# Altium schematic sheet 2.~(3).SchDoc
size 420 x 297 mm
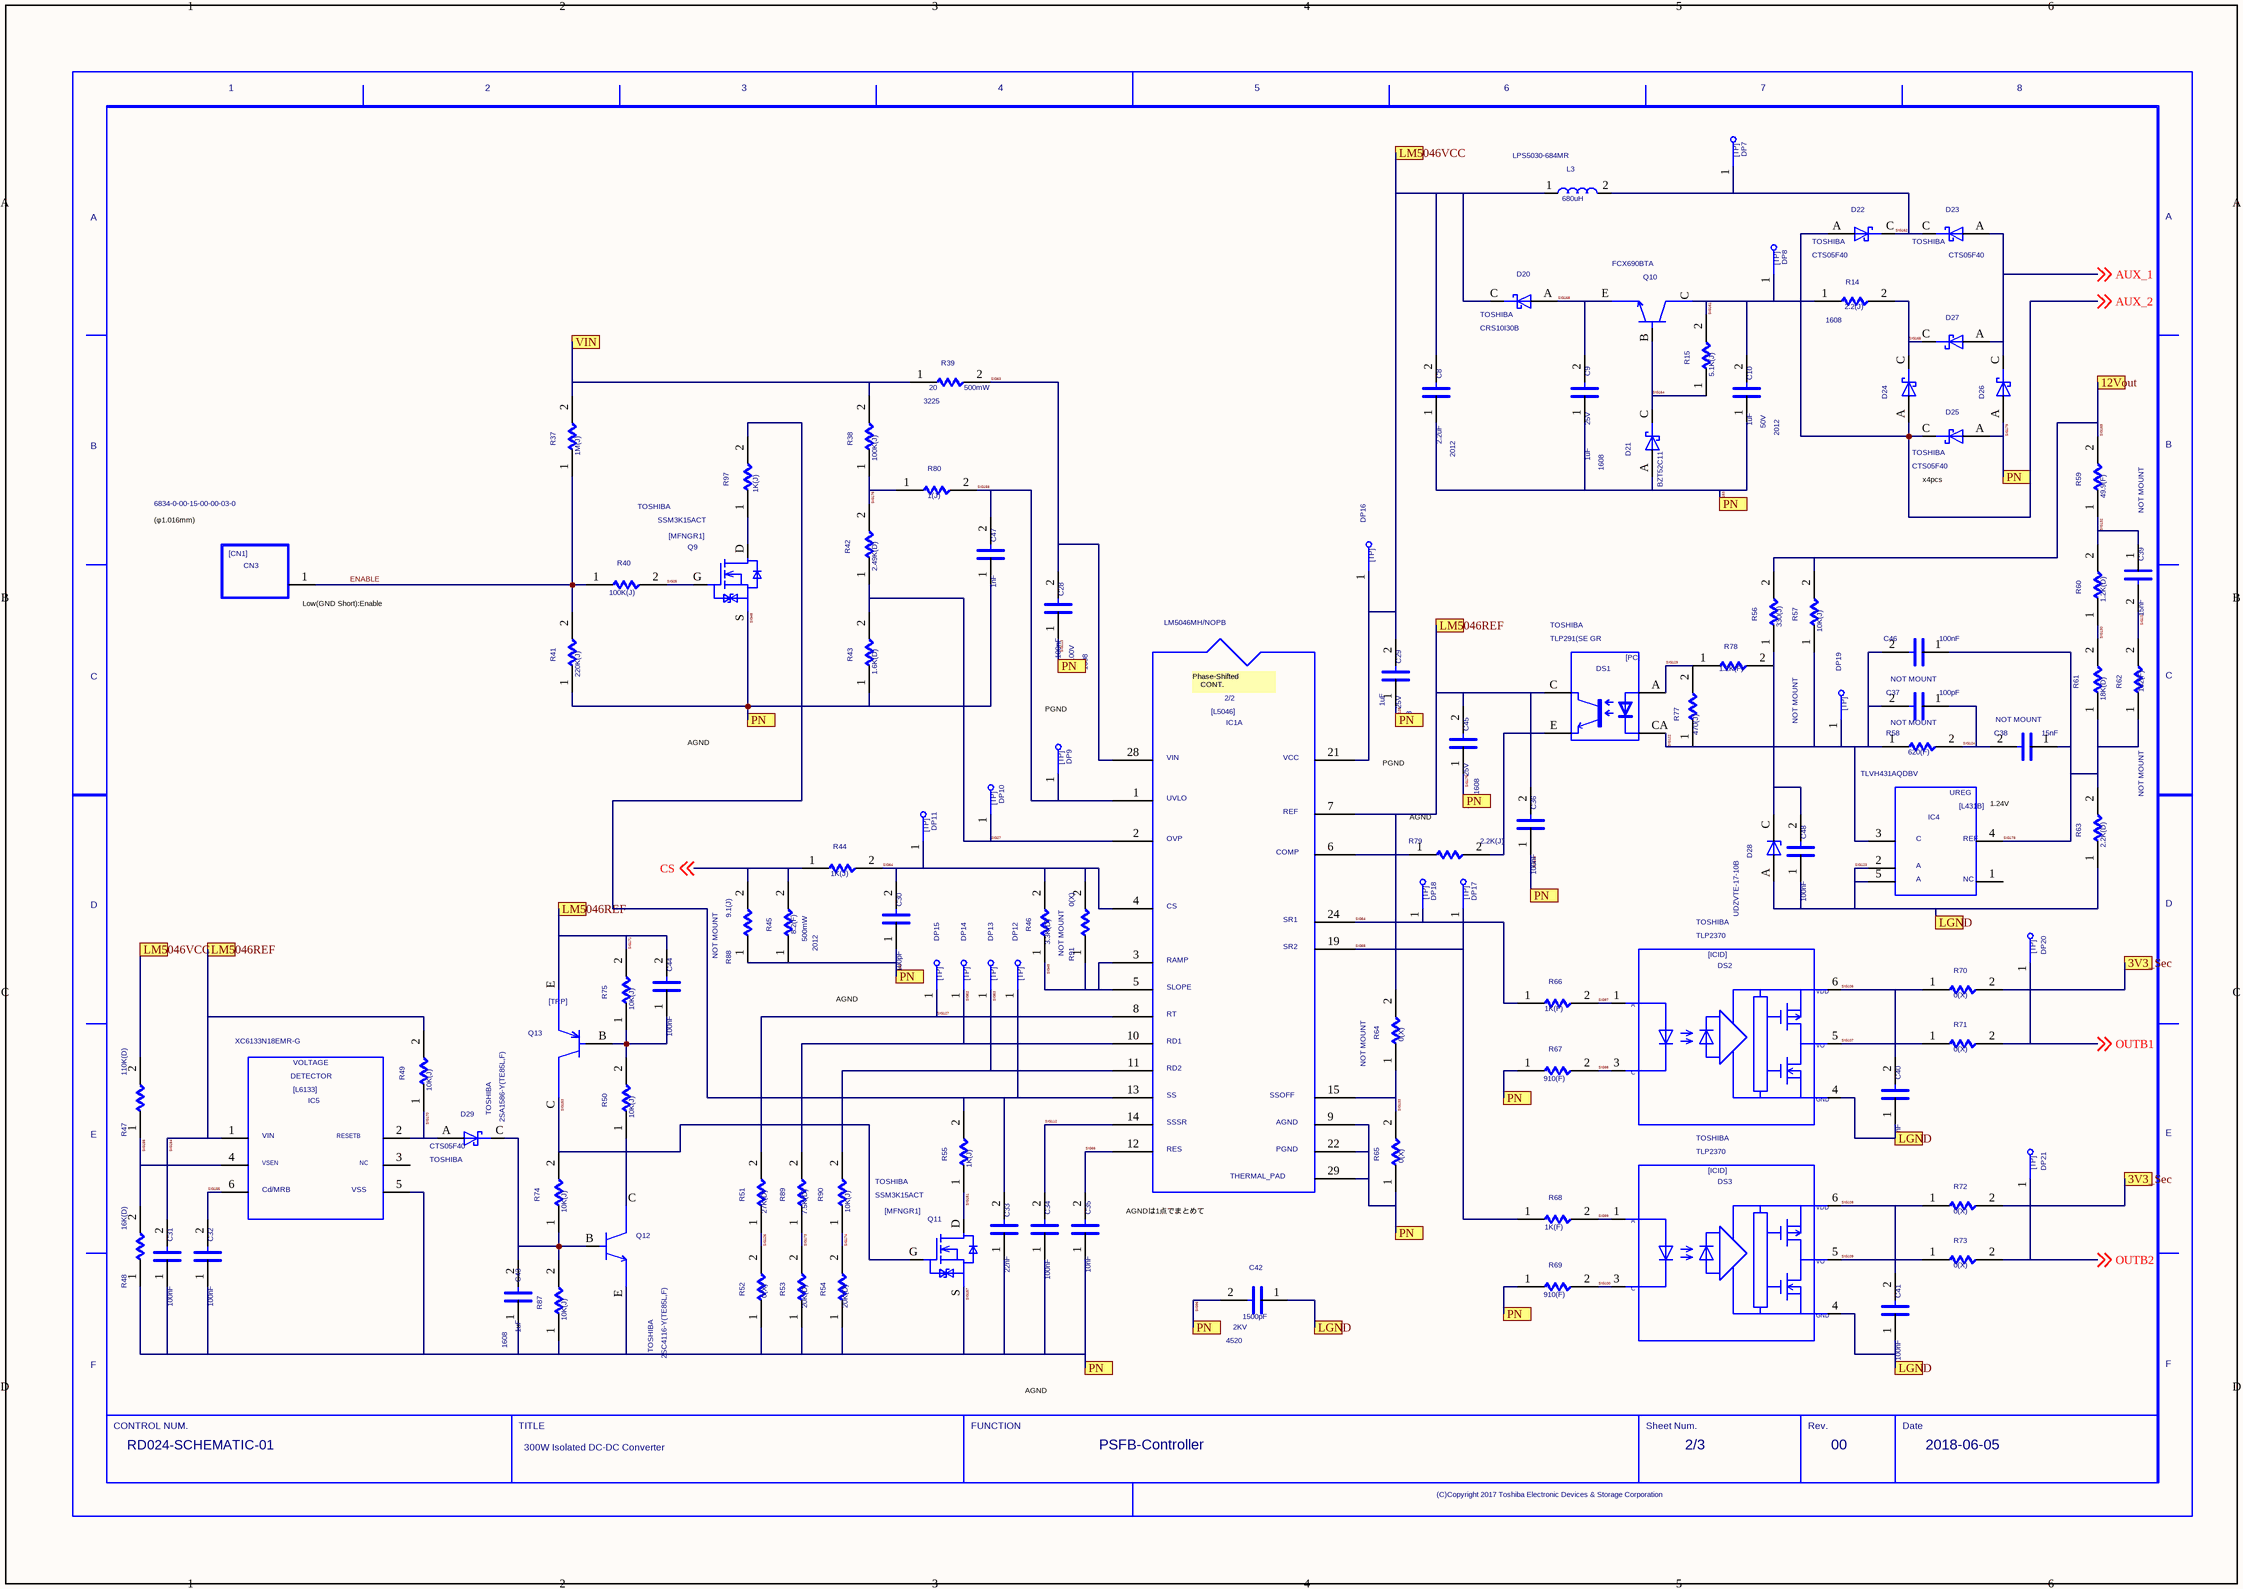
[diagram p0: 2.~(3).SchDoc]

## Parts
C8  2.2uF  SIZECODESMD: 2012
C9  1uF  SIZECODESMD: 1608  VALUE2: 25V
C10  1uF  SIZECODESMD: 2012  VALUE2: 50V
C28  100nF  SIZECODESMD: 1608  VALUE2: 100V
C29  1uF  SIZECODESMD: 1608  VALUE2: 25V
C30  100pF
C31  100nF
C32  100nF
C33  22nF
C34  100nF
C35  10nF
C36  100nF
C37  100pF  NOTMOUNT: NOT MOUNT
C38  15nF  NOTMOUNT: NOT MOUNT
C39  15nF  NOTMOUNT: NOT MOUNT
C40  100nF
C41  100nF
C42  1500pF  SIZECODESMD: 4520  VALUE2: 2KV
C43  1uF  COMPCOMMENT: 1608
C44  100nF
C45  1uF  SIZECODESMD: 1608  VALUE2: 25V
C46  100nF
C47  1nF
C48  100nF
CN3  VALUE3: 6834-0-00-15-00-00-03-0  (hidden comment: CN1)
D20  USERCOMPTEXT3: TOSHIBA  VALUE3: CRS10I30B  (hidden comment: SBD)
D21  VALUE3: BZT52C11  (hidden comment: SBD)
D22  USERCOMPTEXT3: TOSHIBA  VALUE3: CTS05F40  (hidden comment: SBD)
D23  USERCOMPTEXT3: TOSHIBA  VALUE3: CTS05F40  (hidden comment: SBD)
D24  SBD  (value not drawn)
D25  USERCOMPTEXT3: TOSHIBA  VALUE3: CTS05F40  (hidden comment: SBD)
D26  SBD  (value not drawn)
D27  SBD  (value not drawn)
D28  VALUE3: UDZVTE-17-10B  (hidden comment: ZD)
D29  USERCOMPTEXT3: TOSHIBA  VALUE3: CTS05F40  (hidden comment: SBD)
DP7  TP  (value not drawn)
DP8  TP  (value not drawn)
DP9  TP  (value not drawn)
DP10  TP  (value not drawn)
DP11  TP  (value not drawn)
DP12  TP  (value not drawn)
DP13  TP  (value not drawn)
DP14  TP  (value not drawn)
DP15  TP  (value not drawn)
DP16  TP  (value not drawn)
DP17  TP  (value not drawn)
DP18  TP  (value not drawn)
DP19  TP  (value not drawn)
DP20  TP  (value not drawn)
DP21  TP  (value not drawn)
DS1  USERCOMPTEXT3: TOSHIBA  VALUE3: TLP291(SE GR  (hidden comment: PC)
DS2  USERCOMPTEXT3: TOSHIBA  VALUE3: TLP2370  (hidden comment: ICID)
DS3  USERCOMPTEXT3: TOSHIBA  VALUE3: TLP2370  (hidden comment: ICID)
IC1  VALUE3: LM5046MH/NOPB  (hidden comment: L5046_1)  (part A of 2)
IC4  VALUE3: TLVH431AQDBV  (hidden comment: L431B)
IC5  VALUE3: XC6133N18EMR-G  (hidden comment: L6133)
L3  680uH  VALUE3: LPS5030-684MR
Q9  SSM3K15ACT  USERCOMPTEXT3: TOSHIBA
Q10  VALUE3: FCX690BTA  (hidden comment: TRN)
Q11  USERCOMPTEXT3: TOSHIBA  (hidden comment: SSM3K15ACT)
Q12  USERCOMPTEXT3: TOSHIBA  (hidden comment: 2SC4116-Y(TE85L,F))
Q13  USERCOMPTEXT3: TOSHIBA  (hidden comment: 2SA1586-Y(TE85L,F))
R14  2.2(J)  SIZECODESMD: 1608
R15  5.1K(J)
R37  1M(J)
R38  100K(J)
R39  20  SIZECODESMD: 3225  VALUE2: 500mW
R40  100K(J)
R41  220K(J)
R42  2.49K(D)
R43  1.6K(D)
R44  1K(J)
R45  8.2(F)  COMPCOMMENT: 2012  VALUE2: 500mW
R46  3.3K(D)
R47  110K(D)
R48  16K(D)
R49  10K(J)
R50  10K(J)
R51  27K(D)
R52  0(X)
R53  20K(D)
R54  20K(D)
R55  1K(J)
R56  330(J)
R57  10K(J)  NOTMOUNT: NOT MOUNT
R58  620(F)  NOTMOUNT: NOT MOUNT
R59  49.9(F)
R60  1.2K(D)
R61  18K(D)
R62  182(F)  NOTMOUNT: NOT MOUNT
R63  2.2K(D)
R64  0(X)  NOTMOUNT: NOT MOUNT
R65  0(X)
R66  1K(F)
R67  910(F)
R68  1K(F)
R69  910(F)
R70  0(X)
R71  0(X)
R72  0(X)
R73  0(X)
R74  10K(J)
R75  10K(J)
R77  470(J)
R78  1.2K(F)
R79  2.2K(J)
R80  1(J)
R87  10K(J)
R88  9.1(J)  NOTMOUNT: NOT MOUNT
R89  7.5K(D)
R90  10K(J)
R91  0(X)  NOTMOUNT: NOT MOUNT
R97  1K(J)
U?  DATE: 2018-06-05  FUNCTION: PSFB-Controller  DRAWINGNUMBER: RD024-SCHEMATIC-01  TITLE: 300W Isolated DC-DC Converter  REVISION: 00  SHEETNUMBER: 2/3  (hidden comment: WAKU_DEF100)

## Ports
3V3_Sec, 12Vout, LGND, LM5046REF, LM5046VCC, PN, VIN

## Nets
3V3_Sec: R70.2 R72.2 ; port 3V3_Sec
$BN000001: Q9.D R97.1
$BN000002: C48.2 D28.C R56.1 R78.2
$BN000003: C44.1 Q13.B R50.2 R75.1
$BN000004: Q12.C R50.1
$BN000005: DS1.E R79.2
AUX_1: D23.A D26.C D27.A ; off-sheet AUX_1
CS: R44.1 R45.2 R88.2 ; off-sheet CS
ENABLE: CN3.1 R37.1 R40.1 R41.2
LM5046VCC: C8.2 C29.2 D20.C DP16.1 IC1.21 L3.1 R47.2 ; port LM5046VCC
OUTB1: DP20.1 R71.2 ; off-sheet OUTB1
OUTB2: DP21.1 R73.2 ; off-sheet OUTB2
SIG25: Q9.G R40.2
SIG27: DP10.1 IC1.2 R42.1 R43.2
SIG49: IC1.3 IC1.5 R46.1 R91.1
SIG52: DP14.1 IC1.10 R89.2
SIG53: DP13.1 IC1.11 R90.2
SIG54: DP18.1 IC1.24 R66.1
SIG55: DP17.1 IC1.19 R68.1
SIG63: C28.2 IC1.28 R39.2
SIG64: C30.2 DP11.1 IC1.4 R44.2 R46.2 R91.2
SIG66: C35.2 IC1.12
SIG67: C33.2 DP12.1 IC1.13 R55.2 R97.2
SIG74: IC1.6 R79.1
SIG97: DS2.1 R66.2
SIG98: DS2.3 R67.2
SIG99: DS3.1 R68.2
SIG100: DS3.3 R69.2
SIG105: C8.1 C9.1 C10.1 C28.1 C29.1 C30.1 C31.1 C32.1 C33.1 C34.1 C35.1 C36.1 C42.2 C43.1 C45.1 C47.1 D21.A D22.A D24.A D25.A D25.C D26.A IC1.9 IC1.22 IC1.29 IC5.5 Q9.S Q11.S Q12.E R41.1 R43.1 R45.1 R48.1 R52.1 R53.1 R54.1 R65.1 R67.1 R69.1 R87.1 R88.1 ; off-sheet AUX_2, port PN  [also labelled AUX_2, SIG113, SIG128, SIG157, SIG163, SIG175, SIG179, SIG48, SIG65, SIG96]
SIG106: C40.2 DS2.6 R70.1
SIG107: DS2.5 R71.1
SIG108: C41.2 DS3.6 R72.1
SIG109: DS3.5 R73.1
SIG112: C34.2 IC1.14
SIG122: C37.2 C46.2 DP19.1 DS1.CA IC4.3 R57.1 R58.1 R77.1
SIG123: C40.1 C41.1 C42.1 C48.1 D28.A DS2.4 DS3.4 IC4.2 IC4.5 R63.1 ; port LGND
SIG124: C37.1 C38.2 R58.2
SIG126: R51.1 R52.2
SIG127: DP15.1 IC1.8 R51.2
SIG129: DS1.A R77.2 R78.1
SIG130: R60.1 R61.2
SIG131: C39.2 R62.2
SIG132: C39.1 R59.1 R60.2
SIG133: IC1.15 R64.1 R65.2
SIG151: Q11.D R55.1
SIG153: Q11.G Q13.C R74.2
SIG154: C31.2 C36.2 C44.2 C45.2 DS1.C IC1.7 IC5.1 Q13.E R49.2 R64.2 R75.2 ; port LM5046REF  [also labelled SIG171]
SIG155: C32.2 IC5.6
SIG156: IC5.4 R47.1 R48.2
SIG158: C47.2 DP9.1 IC1.1 R80.2
SIG161: C10.2 DP8.1 Q10.C R14.1 R15.2
SIG162: D22.C D23.C DP7.1 L3.2
SIG164: D21.C Q10.B R15.1
SIG165: D24.C D27.C R14.2
SIG168: C9.2 D20.A Q10.E
SIG169: R56.2 R57.2 R59.2 ; port 12Vout
SIG170: D29.A IC5.2 R49.1
SIG172: C43.2 D29.C Q12.B R74.1 R87.2
SIG173: R53.2 R89.1
SIG174: R54.2 R90.1
SIG176: R38.1 R42.2 R80.1
SIG178: C38.1 C46.1 IC4.4 R61.1 R62.1 R63.2
VIN: R37.2 R38.2 R39.1 ; port VIN

Not connected (* = marked no-connect by the designer): IC4 1; IC5 3

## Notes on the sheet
- (φ1.016mm)
- (near D25) x4pcs
- (near CN3) Low(GND Short):Enable
  Open:Disable
- PGND
- AGND
- (near R79) AGND
- 1.24V
- AGNDは1点でまとめて
  IC直近でPGNDと接続する

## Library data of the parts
C8 = C: SQ_PART_MODEL: CON_2.2U; OriginalSymbolOrigin: (2540,7620); RATEDVOLTAGE: 25; MAXGCOUNT: 1; OUMEMAKER: MRT 村田製作所; OUMECLASSIFICATION: セラミックコンデンサ; COMP: PRT_39; NOMINALCAPACITA: 2.2u; ADSCNVFLAG: ON; OUMEMAKERKATAMEI: GRM21BR71E225KA73L@@; ADSCOMPONENTNAME: C_2012; VALUE3: GRM21BR71E225KE11#; VALUE2: 25V; CAPACITANCETOLE: K; ADSMODELNAME: s_GRM21BR71E225KA73L@@
C9 C29 C45 = C: SQ_PART_MODEL: CON_1U; OriginalSymbolOrigin: (2540,7620); RATEDVOLTAGE: 25; MAXGCOUNT: 1; TEMPCHARACTERI2: B; OUMEMAKER: MRT 村田製作所; OUMECLASSIFICATION: セラミックコンデンサ; COMP: PRT_34; NOMINALCAPACITA: 1u; ADSCNVFLAG: ON; OUMEMAKERKATAMEI: GRM188B31E105KA75D; ADSCOMPONENTNAME: C_1608; VALUE3: GRJ188R71E105KE11#; CAPACITANCETOLE: K; CDMASTERCADCELG: KC0008; ADSMODELNAME: s_GRM188B31E105KA75D
C10 = C: SQ_PART_MODEL: CON_1U; OriginalSymbolOrigin: (2540,7620); RATEDVOLTAGE: 50; MAXGCOUNT: 1; OUMEMAKER: MRT 村田製作所; OUMECLASSIFICATION: セラミックコンデンサ; COMP: PRT_33; NOMINALCAPACITA: 1u; ADSCNVFLAG: ON; OUMEMAKERKATAMEI: GCM21BR71H105KA01L@@; ADSCOMPONENTNAME: C_2012; VALUE3: GRJ21BR71H105KE01#; CAPACITANCETOLE: K; CDMASTERCADCELG: KC0136; ADSMODELNAME: s_GCM21BR71H105KA01L@@
C28 = C: SQ_PART_MODEL: CON_100N; OriginalSymbolOrigin: (2540,7620); RATEDVOLTAGE: 100; MAXGCOUNT: 1; OUMEMAKER: MRT 村田製作所; OUMECLASSIFICATION: セラミックコンデンサ; COMP: PRT_51; NOMINALCAPACITA: 100n; ADSCNVFLAG: ON; OUMEMAKERKATAMEI: GRM188R72A104KA35D; ADSCOMPONENTNAME: C_1608; VALUE3: GRM188R72A104KA35#; CAPACITANCETOLE: K; CDMASTERCADCELG: KC0008; ADSMODELNAME: s_GRM188R72A104KA35D
C30 C37 = C: SQ_PART_MODEL: CON_100P; OriginalSymbolOrigin: (2540,7620); RATEDVOLTAGE: 50; MAXGCOUNT: 1; OUMEMAKER: MRT 村田製作所; OUMECLASSIFICATION: セラミックコンデンサ; COMP: PRT_55; SIZECODESMD: 1005; NOMINALCAPACITA: 100p; ADSCNVFLAG: ON; OUMEMAKERKATAMEI: GRM1555C1H101JA01D; ADSCOMPONENTNAME: C_1005; VALUE3: GRM1555C1H101JA01#; VALUE2: 50V; CAPACITANCETOLE: J; CDMASTERCADCELG: KC0005; ADSMODELNAME: s_GRM1555C1H101JA01D
C31 C32 C34 C36 C40 C41 C44 C46 C48 = C: SQ_PART_MODEL: CON_100N; OriginalSymbolOrigin: (2540,7620); RATEDVOLTAGE: 25; MAXGCOUNT: 1; OUMEMAKER: MRT 村田製作所; OUMECLASSIFICATION: セラミックコンデンサ; COMP: PRT_4; SIZECODESMD: 1005; NOMINALCAPACITA: 100n; ADSCNVFLAG: ON; OUMEMAKERKATAMEI: GRM155R71E104KE14D; ADSCOMPONENTNAME: C_1005; VALUE3: GRM155R71E104KE14#; VALUE2: 25V; CAPACITANCETOLE: K; CDMASTERCADCELG: KC0005; ADSMODELNAME: s_GRM155R71E104KE14D
C33 = C: SQ_PART_MODEL: CON_22N; OriginalSymbolOrigin: (2540,7620); RATEDVOLTAGE: 25; MAXGCOUNT: 1; OUMEMAKER: MRT 村田製作所; OUMECLASSIFICATION: セラミックコンデンサ; COMP: PRT_20; SIZECODESMD: 1005; NOMINALCAPACITA: 22n; ADSCNVFLAG: ON; OUMEMAKERKATAMEI: GRM155R71E223KA61D; ADSCOMPONENTNAME: C_1005; VALUE3: GRM155R71E223KA61#; VALUE2: 25V; CAPACITANCETOLE: K; CDMASTERCADCELG: KC0005; ADSMODELNAME: s_GRM155R71E223KA61D
C35 = C: SQ_PART_MODEL: CON_10N; OriginalSymbolOrigin: (2540,7620); RATEDVOLTAGE: 25; MAXGCOUNT: 1; OUMEMAKER: MRT 村田製作所; OUMECLASSIFICATION: セラミックコンデンサ; COMP: PRT_19; SIZECODESMD: 1005; NOMINALCAPACITA: 10n; ADSCNVFLAG: ON; OUMEMAKERKATAMEI: GRM155R71E103KA01D; ADSCOMPONENTNAME: C_1005; VALUE3: GRM155R71E103KA01#; VALUE2: 25V; CAPACITANCETOLE: K; CDMASTERCADCELG: KC0005; ADSMODELNAME: s_GRM155R71E103KA01D
C38 C39 = C: SQ_PART_MODEL: CON_15N; OriginalSymbolOrigin: (2540,7620); RATEDVOLTAGE: 50; MAXGCOUNT: 1; TEMPCHARACTERI2: B; OUMEMAKER: TDK ＴＤＫ; OUMECLASSIFICATION: セラミックコンデンサ; COMP: PRT_23; SIZECODESMD: 1005; NOMINALCAPACITA: 15n; ADSCNVFLAG: ON; OUMEMAKERKATAMEI: C1005JB1H153KT; ADSCOMPONENTNAME: C_1005; VALUE3: GRM155R71E153KA61#; VALUE2: 25V; CAPACITANCETOLE: K; CDMASTERCADCELG: KC0005; ADSMODELNAME: s_C1005JB1H153KT
C42 = C: SQ_PART_MODEL: CON_1N; OriginalSymbolOrigin: (2540,7620); RATEDVOLTAGE: 2K; MAXGCOUNT: 1; OUMEMAKER: MRT 村田製作所; OUMECLASSIFICATION: セラミックコンデンサ; COMP: PRT_22; NOMINALCAPACITA: 1n; ADSCNVFLAG: ON; OUMEMAKERKATAMEI: GR442QR73D102KW01L; ADSCOMPONENTNAME: C_4520; VALUE3: GR442QR73D152KW01-01; CAPACITANCETOLE: K; CDMASTERCADCELG: KC0071; ADSMODELNAME: s_GR442QR73D102KW01L
C43 = C: OriginalSymbolOrigin: (2540,7620); VALUE3: GRJ188R71E105KE11#; VALUE2: 25V; COMP: PRT_5
C47 = C: SQ_PART_MODEL: CON_1N; OriginalSymbolOrigin: (2540,7620); COMP: PRT_50; RATEDVOLTAGE: 50; MAXGCOUNT: 1; TEMPCHARACTERI2: CH; OUMEMAKER: MRT 村田製作所; OUMECLASSIFICATION: セラミックコンデンサ; SIZECODESMD: 1005; NOMINALCAPACITA: 1n; ADSCNVFLAG: ON; OUMEMAKERKATAMEI: GRM1552C1H102JA01D; ADSCOMPONENTNAME: C_1005; VALUE3: GRM155R71H102KA01#; VALUE2: 50V; CAPACITANCETOLE: J; CDMASTERCADCELG: KC0005; ADSMODELNAME: s_GRM1552C1H102JA01D
CN3 = CN1: OriginalSymbolOrigin: (2540,12700); COMP: PRT_16
D20 = SBD: OUMEPARTTYPE: D; SAVEAREA0: -225,-91,12804,7836; TIME: 14:49:55; UPDATEUSER: 19870035; UPDATETIME: 14:20:16; SAVECOUNT: 9; OriginalSymbolOrigin: (5080,5080); MAXGCOUNT: 1; MOUNTINGFORMSMD: SMD; PEAKFORWARDVOLT: 390m; MAXREPETITIVEPE: 30; FORWARDVOLTAGEM: 0; REVERSECURRENT: 60u; CDMASTERCADCELG: MMK0167; OUMEMAKER: TSB 東芝; OUMEMAKERKATAMEI: CRS10I30A; OUMECLASSIFICATION: 高速用整流素子/ショットキバリアダイオード; ADSMODELNAME: s_CRS10I30A; COMP: PRT_49
D21 = SBD: SAVEAREA0: -4630,-153,17114,13055; TIME: 14:49:55; UPDATEUSER: fukuda-y; UPDATETIME: 08:16:22; SAVECOUNT: 9; OriginalSymbolOrigin: (5080,5080); COMP: PRT_35
D22 D23 = SBD: OUMEPARTTYPE: D; SAVEAREA0: -4630,-153,17114,13055; TIME: 14:49:55; UPDATEUSER: fukuda-y; UPDATETIME: 08:16:22; SAVECOUNT: 9; OriginalSymbolOrigin: (5080,5080); FORWARDVOLTAGEM: 0; MAXGCOUNT: 1; MAXREPETITIVEPE: 30; OUMEMAKER: TSB 東芝; MAXAVERAGEFORWA: 500m; MOUNTINGFORMSMD: SMD; OUMECLASSIFICATION: 高速用整流素子/ショットキバリアダイオード; COMP: PRT_48; OUMEMAKERKATAMEI: CTS05S30; CDMASTERCADCELG: KCK0242; ADSMODELNAME: s_CTS05S30
D24 D26 D27 = SBD: SAVEAREA0: -4630,-153,17114,13055; TIME: 14:49:55; UPDATEUSER: fukuda-y; UPDATETIME: 08:16:22; SAVECOUNT: 9; OriginalSymbolOrigin: (5080,5080); USERCOMPTEXT3: TOSHIBA; VALUE3: CTS05F40; COMP: PRT_48
D25 D29 = SBD: SAVEAREA0: -4630,-153,17114,13055; TIME: 14:49:55; UPDATEUSER: fukuda-y; UPDATETIME: 08:16:22; SAVECOUNT: 9; OriginalSymbolOrigin: (5080,5080); COMP: PRT_48
D28 = ZD: SAVEAREA0: -4630,-153,17114,13055; TIME: 14:49:55; UPDATEUSER: fukuda-y; UPDATETIME: 08:18:42; SAVECOUNT: 6; OriginalSymbolOrigin: (5080,5080); COMP: PRT_63
DP7-DP21 = TP: TIME: 16:12:21; UPDATEUSER: fukuda-y; UPDATETIME: 16:18:11; SAVECOUNT: 2; SAVEAREA0: -242,-92,12810,7836; OriginalSymbolOrigin: (0,7620); MAXGCOUNT: 1; COMP: PRT_10
DS1 = PC: OriginalSymbolOrigin: (5080,17780); COMP: PRT_21
DS2 DS3 = ICID: TIME: 11:37:10; UPDATEUSER: cae; UPDATETIME: 10:02:13; SAVECOUNT: 16; SAVEAREA0: -15781,-397,59072,38480; OriginalSymbolOrigin: (2540,35560); COMP: PRT_72
IC1 = L5046_1: SAVEAREA0: -71804,-1007,117827,97484; TIME: 14:38:41; UPDATEUSER: cae; UPDATETIME: 09:49:47; SAVECOUNT: 16; OriginalSymbolOrigin: (7620,93980); CaptureCellPackProp: L5046_1A; COMP: PRT_6
IC4 = L431B: SAVEAREA0: -12224,-318,37706,25614; TIME: 11:47:14; UPDATEUSER: cae; UPDATETIME: 15:43:57; SAVECOUNT: 6; OriginalSymbolOrigin: (5080,22860); COMP: PRT_56
IC5 = L6133: TIME: 13:21:52; UPDATEUSER: cae; UPDATETIME: 10:15:35; SAVECOUNT: 15; SAVEAREA0: -9663,-435,45411,35893; OriginalSymbolOrigin: (5080,33020); COMP: PRT_58
L3 = L: OriginalSymbolOrigin: (2540,5080); RATEDCURRENT: 4.3; INDUCTANCEMAX: 0; MAXGCOUNT: 1; OUMEMAKER: CCT コイルクラフト; MOUNTINGFORMSMD: SMD; OUMECLASSIFICATION: 表面実装用固定コイル; COMP: PRT_37; ADSCNVFLAG: ON; OUMEMAKERKATAMEI: XAL5030-472ME-HDD; ADSCOMPONENTNAME: L_SMD; CDMASTERCADCELG: KCK0316; ADSMODELNAME: s_XAL5030_472ME_HDD; NOMINALINDUCTA2: M; NOMINALINDUCTA1: 4.7u
Q9 Q11 = MFNGR1: OUMEPARTTYPE: Q; SAVECOUNT: 24; SAVEAREA0: -14204,-8572,26849,21288; TIME: 16:49:03; UPDATEUSER: ikeda-k; UPDATETIME: 18:49:38; OriginalSymbolOrigin: (2540,10160); MAXGCOUNT: 1; COMP: PRT_18
Q10 = TRN: TIME: 09:39:04; UPDATEUSER: 19910145; UPDATETIME: 15:12:10; SAVECOUNT: 8; SAVEAREA0: -6194,-158,18648,15662; OriginalSymbolOrigin: (2540,17780); COMP: PRT_36
Q12 = TRN: OUMEPARTTYPE: Q; TIME: 09:39:04; UPDATEUSER: 19910145; UPDATETIME: 15:12:10; SAVECOUNT: 8; SAVEAREA0: -6194,-158,18648,15662; OriginalSymbolOrigin: (2540,17780); MAXGCOUNT: 1; COMP: PRT_62
Q13 = TRP: OUMEPARTTYPE: Q; TIME: 09:39:04; UPDATEUSER: 19870035; UPDATETIME: 15:34:42; SAVECOUNT: 12; SAVEAREA0: -5466,-244,29263,20886; OriginalSymbolOrigin: (5080,22860); MAXGCOUNT: 1; COMP: PRT_61
R14 = R: OriginalSymbolOrigin: (5080,5080); MAXGCOUNT: 1; COMP: PRT_41; VALUE3: ERJ3GEYJ2R2V@@; VALUE2: 100mW
R15 = R: OriginalSymbolOrigin: (5080,5080); MAXGCOUNT: 1; COMP: PRT_40; SIZECODESMD: 1005; VALUE3: ERJ2GEJ512X; VALUE2: 63mW
R37 = R: OriginalSymbolOrigin: (5080,5080); MAXGCOUNT: 1; COMP: PRT_29; SIZECODESMD: 1005; VALUE3: ERJ2GEJ105X; VALUE2: 63mW
R38 R40 = R: OriginalSymbolOrigin: (5080,5080); MAXGCOUNT: 1; COMP: PRT_27; SIZECODESMD: 1005; VALUE3: ERJ2GEJ104X; VALUE2: 63mW
R39 = R: SQ_PART_MODEL: RES_20; OriginalSymbolOrigin: (5080,5080); MAXGCOUNT: 1; OUMEMAKER: NAE パナソニックエレクトロニックデバイス; MOUNTINGFORMSMD: SMD; OUMECLASSIFICATION: 表面実装用固定抵抗器; COMP: PRT_31; RESISTANCETOLER: J; ADSCNVFLAG: ON; POWERRATING: 250m; OUMEMAKERKATAMEI: ERJ14YJ200H; ADSCOMPONENTNAME: R_3225; VALUE3: ERJ14YJ200U; CDMASTERCADCELG: DR903A; ADSMODELNAME: s_ERJ14YJ200H
R41 = R: OriginalSymbolOrigin: (5080,5080); MAXGCOUNT: 1; COMP: PRT_26; SIZECODESMD: 1005; VALUE3: ERJ2GEJ224X; VALUE2: 63mW
R42 = R: OriginalSymbolOrigin: (5080,5080); MAXGCOUNT: 1; COMP: PRT_59; SIZECODESMD: 1005; VALUE3: ERJ2RHD2491X; VALUE2: 63mW
R43 = R: OriginalSymbolOrigin: (5080,5080); VALUE3: ERJ2RHD162X; MAXGCOUNT: 1; COMP: PRT_28; SIZECODESMD: 1005; VALUE2: 63mW
R44 R55 R97 = R: OriginalSymbolOrigin: (5080,5080); MAXGCOUNT: 1; COMP: PRT_30; SIZECODESMD: 1005; VALUE3: ERJ2GEJ102X; VALUE2: 63mW
R45 = R: OriginalSymbolOrigin: (5080,5080); COMP: PRT_57; VALUE3: ERJ6DQF8R2V
R46 = R: OriginalSymbolOrigin: (5080,5080); MAXGCOUNT: 1; COMP: PRT_66; SIZECODESMD: 1005; VALUE3: ERJ2RHD332X; VALUE2: 63mW
R47 = R: OriginalSymbolOrigin: (5080,5080); MAXGCOUNT: 1; COMP: PRT_53; SIZECODESMD: 1005; VALUE3: ERJ2RKD114X; VALUE2: 63mW
R48 = R: OriginalSymbolOrigin: (5080,5080); MAXGCOUNT: 1; COMP: PRT_54; SIZECODESMD: 1005; VALUE3: ERJ2RHD163X; VALUE2: 63mW
R49 R50 R57 R74 R75 R87 R90 = R: OriginalSymbolOrigin: (5080,5080); MAXGCOUNT: 1; COMP: PRT_8; SIZECODESMD: 1005; VALUE3: ERJ2GEJ103X; VALUE2: 63mW
R51 = R: OriginalSymbolOrigin: (5080,5080); MAXGCOUNT: 1; COMP: PRT_65; SIZECODESMD: 1005; VALUE3: ERJ2RHD273X; VALUE2: 63mW
R52 R64 R65 R70-R73 R91 = R: OriginalSymbolOrigin: (5080,5080); MAXGCOUNT: 1; COMP: PRT_25; SIZECODESMD: 1005; VALUE3: ERJ2GE0R00X; VALUE2: 63mW
R53 R54 = R: OriginalSymbolOrigin: (5080,5080); MAXGCOUNT: 1; COMP: PRT_52; SIZECODESMD: 1005; VALUE3: ERJ2RHD203X; VALUE2: 63mW
R56 = R: OriginalSymbolOrigin: (5080,5080); MAXGCOUNT: 1; COMP: PRT_71; SIZECODESMD: 1005; VALUE3: ERJ2GEJ331X; VALUE2: 63mW
R58 = R: OriginalSymbolOrigin: (5080,5080); MAXGCOUNT: 1; COMP: PRT_70; SIZECODESMD: 1005; VALUE3: ERJ2RKF6200X; VALUE2: 63mW
R59 = R: OriginalSymbolOrigin: (5080,5080); MAXGCOUNT: 1; COMP: PRT_24; SIZECODESMD: 1005; VALUE3: ERJ2RKF49R9X; VALUE2: 63mW
R60 = R: OriginalSymbolOrigin: (5080,5080); MAXGCOUNT: 1; COMP: PRT_42; SIZECODESMD: 1005; VALUE3: ERJ2RHD122X; VALUE2: 63mW; UPDATETIME: 18:40:58; UPDATEUSER: user1; TIME: 13:31:56; SAVEAREA0: -17703,-20267,33725,19386; MONOCODE: E00000333
R61 = R: OriginalSymbolOrigin: (5080,5080); MAXGCOUNT: 1; COMP: PRT_43; SIZECODESMD: 1005; VALUE3: ERJ2RHD183X; VALUE2: 63mW
R62 = R: OriginalSymbolOrigin: (5080,5080); MAXGCOUNT: 1; COMP: PRT_60; SIZECODESMD: 1005; VALUE3: RC0402FR-07182RL; VALUE2: 63mW
R63 = R: OriginalSymbolOrigin: (5080,5080); MAXGCOUNT: 1; COMP: PRT_44; SIZECODESMD: 1005; VALUE3: ERJ2RHD222X; VALUE2: 63mW
R66 R68 = R: OriginalSymbolOrigin: (5080,5080); MAXGCOUNT: 1; COMP: PRT_45; SIZECODESMD: 1005; VALUE3: ERJ2RKF1001X; VALUE2: 63mW
R67 R69 = R: OriginalSymbolOrigin: (5080,5080); MAXGCOUNT: 1; COMP: PRT_46; SIZECODESMD: 1005; VALUE3: RK73H1ETTP9100F; VALUE2: 63mW
R77 = R: OriginalSymbolOrigin: (5080,5080); MAXGCOUNT: 1; COMP: PRT_68; SIZECODESMD: 1005; VALUE3: ERJ2GEJ471X; VALUE2: 63mW
R78 = R: OriginalSymbolOrigin: (5080,5080); MAXGCOUNT: 1; COMP: PRT_69; SIZECODESMD: 1005; VALUE3: ERJ2RKF1201X; VALUE2: 63mW
R79 = R: OriginalSymbolOrigin: (5080,5080); MAXGCOUNT: 1; COMP: PRT_67; SIZECODESMD: 1005; VALUE3: ERJ2GEJ222X; VALUE2: 63mW
R80 = R: OriginalSymbolOrigin: (5080,5080); MAXGCOUNT: 1; COMP: PRT_32; SIZECODESMD: 1005; VALUE3: ERJ2GEJ1R0X; VALUE2: 63mW
R88 = R: OriginalSymbolOrigin: (5080,5080); MAXGCOUNT: 1; COMP: PRT_47; SIZECODESMD: 1005; VALUE3: ERJ2GEJ9R1X; VALUE2: 63mW
R89 = R: OriginalSymbolOrigin: (5080,5080); MAXGCOUNT: 1; COMP: PRT_64; SIZECODESMD: 1005; VALUE3: ERJ2RHD752X; VALUE2: 63mW
U? = WAKU_DEF100: PLOTTIME: HH:MM; SAVEAREA0: -45080,-4508,463680,304612; TIME: 11:06:15; UPDATEUSER: d5009410; UPDATETIME: 14:09:25; SAVECOUNT: 3; OriginalSymbolOrigin: (10160,284480); PAGENUMBER: 03; DESIGNED: TOSHIBA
